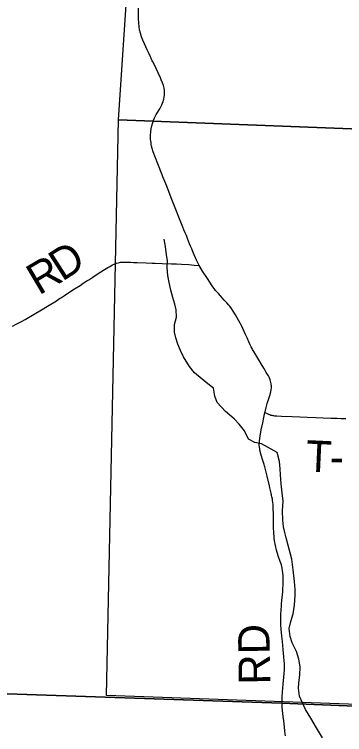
# Model space of a CAD drawing. Extents: x 0 to 34, y 0 to 22.
# Drawn here: x 29.474 to 30.071, y 18.143 to 19.446 of the extents above; entities that cross this region are included whole.
import ezdxf

# ---------------------------------------------------------------- set-up
doc = ezdxf.new("R2010")
doc.units = 0
for name, color, linetype in [('GM_X_County_Road', 7, 'Continuous'), ('GM_X_County_Road_Text', 7, 'Continuous'), ('GM_X_Minor_River', 7, 'Continuous'), ('GM_X_Section', 7, 'Continuous'), ('GM_X_Township', 7, 'Continuous'), ('GM_X_Township_Road', 7, 'Continuous'), ('GM_X_Township_Road_Text', 7, 'Continuous')]:
    doc.layers.add(name, color=color, linetype=linetype)

msp = doc.modelspace()

# ---------------------------------------------------------------- linework, layer by layer
at = {"layer": 'GM_X_County_Road'}
for points in [[(29.8077, 18.9919), (29.8032, 19.0013), (29.7971, 19.015), (29.7943, 19.0217), (29.7923, 19.0266), (29.7905, 19.031), (29.7867, 19.0407), (29.7846, 19.0462), (29.7825, 19.0511), (29.7803, 19.0563), (29.7784, 19.0614), (29.776, 19.0672), (29.7725, 19.0761), (29.7658, 19.093), (29.7572, 19.1143), (29.749, 19.1352), (29.7423, 19.1521), (29.7409, 19.1555), (29.7333, 19.1758), (29.7247, 19.1976), (29.7228, 19.2036), (29.7218, 19.2078), (29.7211, 19.2111), (29.7207, 19.2141), (29.7203, 19.2172), (29.72, 19.22), (29.7198, 19.2225), (29.7198, 19.2276), (29.7201, 19.2335), (29.7208, 19.2391), (29.722, 19.2444), (29.7237, 19.2504), (29.7254, 19.255), (29.7271, 19.2587), (29.7291, 19.2627), (29.7303, 19.2651), (29.7365, 19.2752), (29.7377, 19.2774), (29.7402, 19.2824), (29.7426, 19.2887), (29.7433, 19.2909), (29.7438, 19.2929), (29.7446, 19.2965), (29.7451, 19.2997), (29.7453, 19.3039), (29.7451, 19.3082), (29.7443, 19.3127), (29.7431, 19.3174), (29.7414, 19.3221), (29.7392, 19.3278), (29.7378, 19.3311), (29.7334, 19.3406), (29.7298, 19.3484), (29.7262, 19.3558), (29.724, 19.3603), (29.723, 19.3622), (29.7212, 19.366), (29.7207, 19.367), (29.7196, 19.3695), (29.7172, 19.3747), (29.7138, 19.3821), (29.709, 19.3926), (29.706, 19.3993), (29.7036, 19.4056), (29.7016, 19.4121), (29.7001, 19.4181), (29.6991, 19.4243), (29.6984, 19.4304), (29.6983, 19.4387), (29.698, 19.4572)], [(29.9268, 18.726), (29.9271, 18.727), (29.9289, 18.7348), (29.9309, 18.7423), (29.9336, 18.7513), (29.9353, 18.7567), (29.9372, 18.763), (29.938, 18.7671), (29.9384, 18.7699), (29.9383, 18.7737), (29.938, 18.7774), (29.9375, 18.7799), (29.937, 18.7824), (29.9363, 18.7847), (29.9356, 18.7865), (29.9343, 18.7895), (29.9331, 18.792), (29.9292, 18.7983), (29.9279, 18.8004), (29.9271, 18.8018), (29.9247, 18.8057), (29.9197, 18.814), (29.9154, 18.8211), (29.9119, 18.8269), (29.9064, 18.8359), (29.9043, 18.8396), (29.9034, 18.8414), (29.9018, 18.8447), (29.8999, 18.8484), (29.8975, 18.8538), (29.8944, 18.861), (29.8912, 18.8681), (29.8849, 18.8818), (29.8796, 18.8917), (29.8737, 18.9023), (29.8694, 18.9089), (29.866, 18.914), (29.8631, 18.9179), (29.8617, 18.9198), (29.8578, 18.9243), (29.8532, 18.9293), (29.8428, 18.9409), (29.8374, 18.9467), (29.836, 18.9485), (29.8315, 18.9551), (29.8273, 18.9614), (29.8228, 18.9683), (29.8141, 18.9815), (29.8077, 18.9919)], [(29.9638, 18.1407), (29.9636, 18.1446), (29.963, 18.1494), (29.962, 18.1568), (29.9606, 18.1681), (29.9596, 18.1757), (29.9585, 18.1864), (29.958, 18.1932), (29.9576, 18.1988), (29.9576, 18.1996), (29.9576, 18.2054), (29.9578, 18.2114), (29.9585, 18.2197), (29.9597, 18.2344), (29.9606, 18.247), (29.9618, 18.26), (29.962, 18.2631), (29.9622, 18.2668), (29.962, 18.2716), (29.9617, 18.2765), (29.9611, 18.2835), (29.9598, 18.2967), (29.9582, 18.3113), (29.9571, 18.3209), (29.9561, 18.3338), (29.9556, 18.3411), (29.9554, 18.3477), (29.9552, 18.3533), (29.9555, 18.3605), (29.9559, 18.369), (29.9564, 18.3762), (29.9567, 18.3797), (29.9573, 18.3859), (29.9583, 18.3959), (29.9588, 18.4015), (29.9591, 18.407), (29.9594, 18.4138), (29.9596, 18.4208), (29.9594, 18.4297), (29.9589, 18.4364), (29.9586, 18.4394), (29.9578, 18.4441), (29.9564, 18.4501), (29.9545, 18.4563), (29.9514, 18.4647), (29.9488, 18.4726), (29.9475, 18.4768), (29.9468, 18.4796), (29.9462, 18.4821), (29.9457, 18.4851), (29.9451, 18.4881), (29.9446, 18.4908), (29.9441, 18.4943), (29.9436, 18.4984), (29.9432, 18.5022), (29.943, 18.5063), (29.9427, 18.5099), (29.9425, 18.5159), (29.9423, 18.5229), (29.9422, 18.5353), (29.9421, 18.5423), (29.9418, 18.5516), (29.9416, 18.5566), (29.9414, 18.5596), (29.9411, 18.563), (29.9406, 18.5664), (29.9401, 18.5692), (29.9394, 18.573), (29.9388, 18.5757), (29.9385, 18.577), (29.9381, 18.5788), (29.9378, 18.58), (29.9358, 18.5892), (29.9349, 18.5931), (29.9308, 18.6104), (29.9285, 18.62), (29.927, 18.6253), (29.9263, 18.6277), (29.9259, 18.6295), (29.9252, 18.6319), (29.9247, 18.6337), (29.9231, 18.6391), (29.9201, 18.6485), (29.9182, 18.6551), (29.9172, 18.6594), (29.9166, 18.6638), (29.9164, 18.6666), (29.9164, 18.6692), (29.9166, 18.672), (29.9168, 18.6743), (29.918, 18.6828), (29.92, 18.6942), (29.9228, 18.7073), (29.9247, 18.7168), (29.9268, 18.726)]]:
    msp.add_lwpolyline(points, dxfattribs=at)
at = {"layer": 'GM_X_Minor_River'}
msp.add_lwpolyline([(30.0309, 18.1374), (30.0198, 18.1555), (30.0098, 18.1725), (29.9998, 18.1883), (29.9893, 18.2125), (29.9873, 18.2268), (29.988, 18.2363), (29.9901, 18.2511), (29.9907, 18.2655), (29.9883, 18.2795), (29.984, 18.2935), (29.9759, 18.3093), (29.9721, 18.3207), (29.9708, 18.3347), (29.9737, 18.3476), (29.9777, 18.3613), (29.9799, 18.3772), (29.9816, 18.3954), (29.9811, 18.4057), (29.9802, 18.42), (29.9777, 18.4412), (29.9753, 18.4602), (29.9706, 18.4787), (29.9651, 18.4987), (29.9624, 18.5089), (29.9604, 18.5188), (29.9588, 18.5309), (29.9586, 18.5479), (29.9596, 18.5654), (29.9579, 18.5805), (29.9559, 18.5964), (29.955, 18.6131), (29.9545, 18.6237), (29.9532, 18.6369), (29.9489, 18.6536), (29.9326, 18.6625), (29.9208, 18.6692), (29.9086, 18.6717), (29.8972, 18.6777), (29.8899, 18.6928), (29.8799, 18.7044), (29.8708, 18.7142), (29.8551, 18.7277), (29.8402, 18.7438), (29.8363, 18.7552), (29.8335, 18.7699), (29.8233, 18.7778), (29.7996, 18.7976), (29.7904, 18.8089), (29.7793, 18.8266), (29.7739, 18.8379), (29.7692, 18.8496), (29.7657, 18.861), (29.7634, 18.8712), (29.7632, 18.8848), (29.7665, 18.8985), (29.766, 18.9114), (29.7636, 18.922), (29.7601, 18.934), (29.7566, 18.9473), (29.7538, 18.9609), (29.7514, 18.9738), (29.7498, 18.9878), (29.7508, 19.001), (29.7488, 19.0109), (29.7468, 19.026), (29.7444, 19.0392)], dxfattribs=at)
at = {"layer": 'GM_X_Section'}
for points in [[(30.7049, 20.2326), (30.6447, 19.2173), (29.6621, 19.2554), (29.7299, 20.2792)], [(30.6447, 19.2173), (30.6169, 18.1787), (29.6404, 18.2139), (29.6621, 19.2554)]]:
    msp.add_lwpolyline(points, close=True, dxfattribs=at)
at = {"layer": 'GM_X_Township'}
for points in [[(28.7526, 20.9), (28.7366, 20.4185), (28.7263, 19.9342), (28.6656, 18.2443), (29.0347, 18.2309), (29.9568, 18.1999), (30.8167, 18.1651)], [(30.8167, 18.1651), (29.9568, 18.1999), (29.0347, 18.2309), (28.6656, 18.2443), (28.6433, 17.8576), (28.637, 17.506), (28.6368, 17.4981), (28.5999, 16.6109), (28.5991, 16.5887), (28.5955, 16.4142)]]:
    msp.add_lwpolyline(points, dxfattribs=at)
at = {"layer": 'GM_X_Township_Road'}
for points in [[(29.4702, 18.8821), (29.4769, 18.8854), (29.4862, 18.8903), (29.4932, 18.8942), (29.5093, 18.9035), (29.5226, 18.9116), (29.5332, 18.918), (29.5495, 18.928), (29.5536, 18.9306), (29.5604, 18.935), (29.564, 18.9373), (29.5666, 18.939), (29.5826, 18.9493), (29.5925, 18.9558), (29.5981, 18.9596), (29.6048, 18.9639), (29.6083, 18.9661), (29.6152, 18.9706), (29.6233, 18.9758), (29.6366, 18.9846), (29.6393, 18.9861), (29.6424, 18.9881), (29.6451, 18.9896), (29.651, 18.9927), (29.6542, 18.9941), (29.6583, 18.9957), (29.6615, 18.9967), (29.6636, 18.9971), (29.6658, 18.9975), (29.6683, 18.9977), (29.6737, 18.9978), (29.6786, 18.9977), (29.6842, 18.9975), (29.6892, 18.9974), (29.6959, 18.997), (29.7117, 18.9964), (29.7228, 18.9961), (29.7282, 18.9959), (29.7408, 18.9954), (29.7578, 18.9949), (29.7669, 18.9946), (29.7756, 18.9942), (29.7888, 18.9933), (29.7985, 18.9925), (29.8077, 18.9919)], [(29.9268, 18.726), (29.9306, 18.7241), (29.9332, 18.7229), (29.9355, 18.7219), (29.9375, 18.7212), (29.939, 18.7208), (29.9408, 18.7203), (29.9422, 18.7201), (29.9441, 18.7198), (29.9484, 18.7195), (29.9569, 18.719), (29.9762, 18.7184), (29.9901, 18.7179), (30.0033, 18.7175), (30.0188, 18.7169), (30.0323, 18.7164), (30.0461, 18.7158), (30.0574, 18.7154), (30.0645, 18.7151), (30.0692, 18.715), (30.0728, 18.715)]]:
    msp.add_lwpolyline(points, dxfattribs=at)

# ---------------------------------------------------------------- texts
at = {"layer": 'GM_X_County_Road_Text'}
msp.add_text('RD', height=0.05682, rotation=90.9872, dxfattribs=at).set_placement((29.9364, 18.2338))
at = {"layer": 'GM_X_Township_Road_Text'}
for s, rotation, p in [('D', 32.7662, (29.56, 18.962)), ('R', 30.6371, (29.5179, 18.937)), ('T', 357.3805, (29.9996, 18.6191)), ('-', 359.1615, (30.0439, 18.6171))]:
    msp.add_text(s, height=0.0568, rotation=rotation, dxfattribs=at).set_placement(p)

doc.saveas('drawing.dxf')
